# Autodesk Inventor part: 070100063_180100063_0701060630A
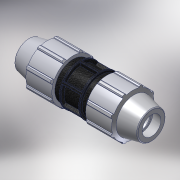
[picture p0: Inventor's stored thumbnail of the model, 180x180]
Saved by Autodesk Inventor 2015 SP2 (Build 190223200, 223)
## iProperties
Created: 2017-02
Part Number: 070100063_180100063_0701060630A
Material: PVC-Piping
Description: PLASSON COUPLER 63-63
Document SubType Name: Modeling
Designer: KIM
Mass: 92.6774 g
Surface Area: 199.44 cm^2
Volume: 66.1981 cm^3
Density: 1.4 g/cm^3
Appearance: PTFE
Author: KIM
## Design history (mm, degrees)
derived "07010.ipt"
feature "Solid1::07010.ipt"
tag "TaggingFeature1"
body "Solid1"
other parameters: "d2" = 63, "d4" = 19.16667, "d5" = 32.85714, "d7" = 113, "d8" = 84.75, "d9" = 32.85714, "d11" = 3.28571, "d12" = 90.4, "d13" = 120 deg, "d14" = 88.2, "d15" = 6 deg, "d16" = 101.7, "d18" = 3.15, "d19" = 35 deg, "d20" = 17.5 deg, "d21" = 105.09, "d23" = 0, "d25" = 360 deg, "d27" = 2.26, "d33" = 1.26, "d34" = 5.65, "d36" = 0, "d37" = 1.26, "d38" = 1.26, "d40" = 360 deg, "d42" = 50.6, "d43" = 3.39, "d46" = 1.89, "d49" = 113, "d50" = 50.4, "d_" = 63, "E_" = 113, "l_" = 113
